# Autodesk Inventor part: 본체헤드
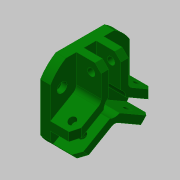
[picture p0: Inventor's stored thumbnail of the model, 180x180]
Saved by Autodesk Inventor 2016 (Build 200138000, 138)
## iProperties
Created: 2020-02
Part Number: 본체헤드
Material: 알루미늄 6061
Document SubType Name: Modeling
Designer: mduedu
Density: 1 g/cm^3
Appearance: 진녹색
Author: mduedu
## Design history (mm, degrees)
sketch "스케치1"
  geometry: L1 (-32, -32)-(32, -32); L2 (32, -32)-(32, 32); L3 (32, 32)-(-32, 32); L4 (-32, 32)-(-32, -32); L5 (-32, -32)-(32, 32); L6 (32, -32)-(-32, 32); 1 further point
  constraints: 12 end point, 2 midpoint, 2 parallel, 1 horizontal, 1 perpendicular
  dimensions: "d0" = 64 distance of L3.end L2.end; "d1" = 64 distance of L2.end L1.end
extrude "돌출1" new body sketch "스케치1" distance "d2" = 28; taper "d3" = 0 deg
sketch "스케치2"
  geometry: C1 r 37.5 at (0, 0); 1 further point
  constraints: 1 centre point, 1 coincident
  dimensions: "d4" = 75 diameter of C1
extrude "돌출2" sketch "스케치2" stored distance "d5" = 28; taper "d6" = 0 deg
sketch "스케치3"
  geometry: C1 r 20 at (0, 0); 1 further point
  constraints: 1 centre point, 1 coincident
  dimensions: "d7" = 40 diameter of C1
extrude "돌출3" join sketch "스케치3" distance "d8" = 12; taper "d9" = 0 deg
sketch "스케치4"
  geometry: L1 (-32, 19.551)-(-32, -19.551) reference; L2 (-19.551, -32)-(19.551, -32) reference; L3 (32, -19.551)-(32, 19.551) reference; L4 (19.551, 32)-(-19.551, 32) reference; L5 (0, 0)-(0, 37.5); L6 (0, 0)-(32.476, -18.75); L7 (0, 0)-(-32.476, -18.75); L8 (11, 6.351)-(11, 35.85); L9 (-11, 6.351)-(-11, 35.85); L10 (-11, 6.351)-(-36.547, -8.399); L11 (0, -12.702)-(-25.547, -27.451); L12 (11, 6.351)-(36.547, -8.399); L13 (0, -12.702)-(25.547, -27.451); L14 (-5, 2.887)-(-5, 37.165); L15 (5, 2.887)-(5, 37.165); L16 (-5, 2.887)-(-34.686, -14.252); L17 (0, -5.774)-(-29.686, -22.913); L18 (0, -5.774)-(29.686, -22.913); L19 (5, 2.887)-(34.686, -14.252); A1 r 37.5 centre (0, 0) between (-19.551, 32) and (-32, 19.551) reference; A2 r 37.5 centre (0, 0) between (-32, -19.551) and (-19.551, -32) reference; A3 r 37.5 centre (0, 0) between (19.551, -32) and (32, -19.551) reference; A4 r 37.5 centre (0, 0) between (32, 19.551) and (19.551, 32) reference; 1 further point
  constraints: 30 end point, 12 parallel, 2 point on circle, 1 coincident, 1 perpendicular, 24 other
  dimensions: "d10" = 120 deg angle of L6 L5; "d11" = 120 deg angle of L7 L6; "d12" = 22 distance between parallel lines of L8 L9; "d14" = 22 distance between parallel lines of L11 L10; "d15" = 22 distance between parallel lines of L12 L13; "d18" = 10 distance between parallel lines of L15 L14; "d19" = 10 distance between parallel lines of L18 L19; "d20" = 10 distance between parallel lines of L16 L17
  node "투영된 루프1"
extrude "돌출4" cut sketch "스케치4" distance "d16" = 20; taper "d17" = 0 deg
extrude "돌출5" cut sketch "스케치4" distance "d21" = 20; taper "d22" = 0 deg
sketch "스케치5"
  geometry: C1 r 9 at (0, 0); 1 further point
  constraints: 1 centre point, 1 coincident
  dimensions: "d23" = 18 diameter of C1
extrude "돌출6" cut sketch "스케치5" stored distance "d24" = 20; taper "d25" = 0 deg
sketch "스케치6"
  geometry: L1 (32, 0)-(19.551, 0) reference; C1 r 3 at (24, 20); 1 further point
  constraints: 1 centre point
  dimensions: "d26" = 6 diameter of C1; "d27" = 24 horizontal distance of C1.centre point (0, 0); "d28" = 20 distance from line of C1.centre L1
extrude "돌출7" cut sketch "스케치6" stored distance "d29" = 20; taper "d30" = 0 deg
sketch "스케치7"
  geometry: L1 (-20, -12)-(-20, 0) reference; L2 (-20, 0)-(-32, 0) reference; L3 (-32, 0)-(-32, 8) reference; L4 (-32, 8)-(-12.702, 8) reference; L5 (-12.702, 8)-(-12.702, 28) reference; L6 (-12.702, 28)-(-9, 28) reference; L7 (-9, 28)-(-9, -12) reference; L8 (-9, -12)-(-20, -12) reference; L9 (20, 0)-(20, -12) reference; L10 (20, -12)-(9, -12) reference; L11 (9, -12)-(9, 8) reference; L12 (9, 8)-(32, 8) reference; L13 (32, 8)-(32, 0) reference; L14 (32, 0)-(20, 0) reference; L15 (20, -8.35)-(17, -8.35); L16 (17, -8.35)-(17, -3.65); L17 (17, -3.65)-(20, -3.65); L18 (20, -3.65)-(20, -8.35); L19 (9, -2.4)-(11, -2.4); L20 (11, -2.4)-(11, -5.6); L21 (11, -5.6)-(9, -5.6); L22 (9, -5.6)-(9, -2.4); L23 (0, -20)-(0, 36) reference; L24 (17, -6)-(20, -6); L25 (11, -4)-(9, -4); 1 further point
  constraints: 20 end point, 4 midpoint, 4 parallel, 2 horizontal, 2 perpendicular, 2 point on line
  dimensions: "d34" = 6 distance between parallel lines of L24 L14; "d35" = 34 diameter of L16 L23; "d36" = 4.7 distance between parallel lines of L17 L15; "d37" = 8 distance between parallel lines of L25 L10; "d38" = 3.2 distance of L19.end L20.end; "d39" = 22 diameter of L20 L23
revolve "회전1" sketch "스케치7" stored, may be unused: angle "d40" = 90 deg
fillet "모깎기1" dims "d41" = 0.8
fillet "모깎기2" dims "d42" = 0.4
chamfer "모따기1" distance "d43" = 0.3; stored, may be unused: second distance "d44" = 2, angle "d45" = 45 deg
chamfer "모따기2" distance "d46" = 0.3; stored, may be unused: second distance "d47" = 2, angle "d48" = 45 deg
chamfer "모따기3" distance "d49" = 1; stored, may be unused: second distance "d50" = 2, angle "d51" = 45 deg
fillet "모깎기3" dims "d52" = 5
chamfer "모따기4" distance "d53" = 5; stored, may be unused: second distance "d54" = 2, angle "d55" = 45 deg
sketch "스케치8" dims "d56" = 52
  geometry: 3 further points
  constraints: 2 vertical alignment, 1 coincident, 2 other
hole "구멍1" sketch "스케치8" at (0, -26) diameter "d57" = 4.5; stored, may be unused: countersink angle "d61" = 90 deg, drill point angle "d63" = 118 deg; dims "d58" = 6, "d59" = 8, "d60" = 4.4, "d62" = 8
node "작업 평면1"
node "작업 평면2"
node "솔리드1"
pattern_circular "원형 패턴1" dims angle "d32" = 360 deg
pattern_circular "원형 패턴2" dims angle "d65" = 360 deg
node "절단 모서리 투영1"
